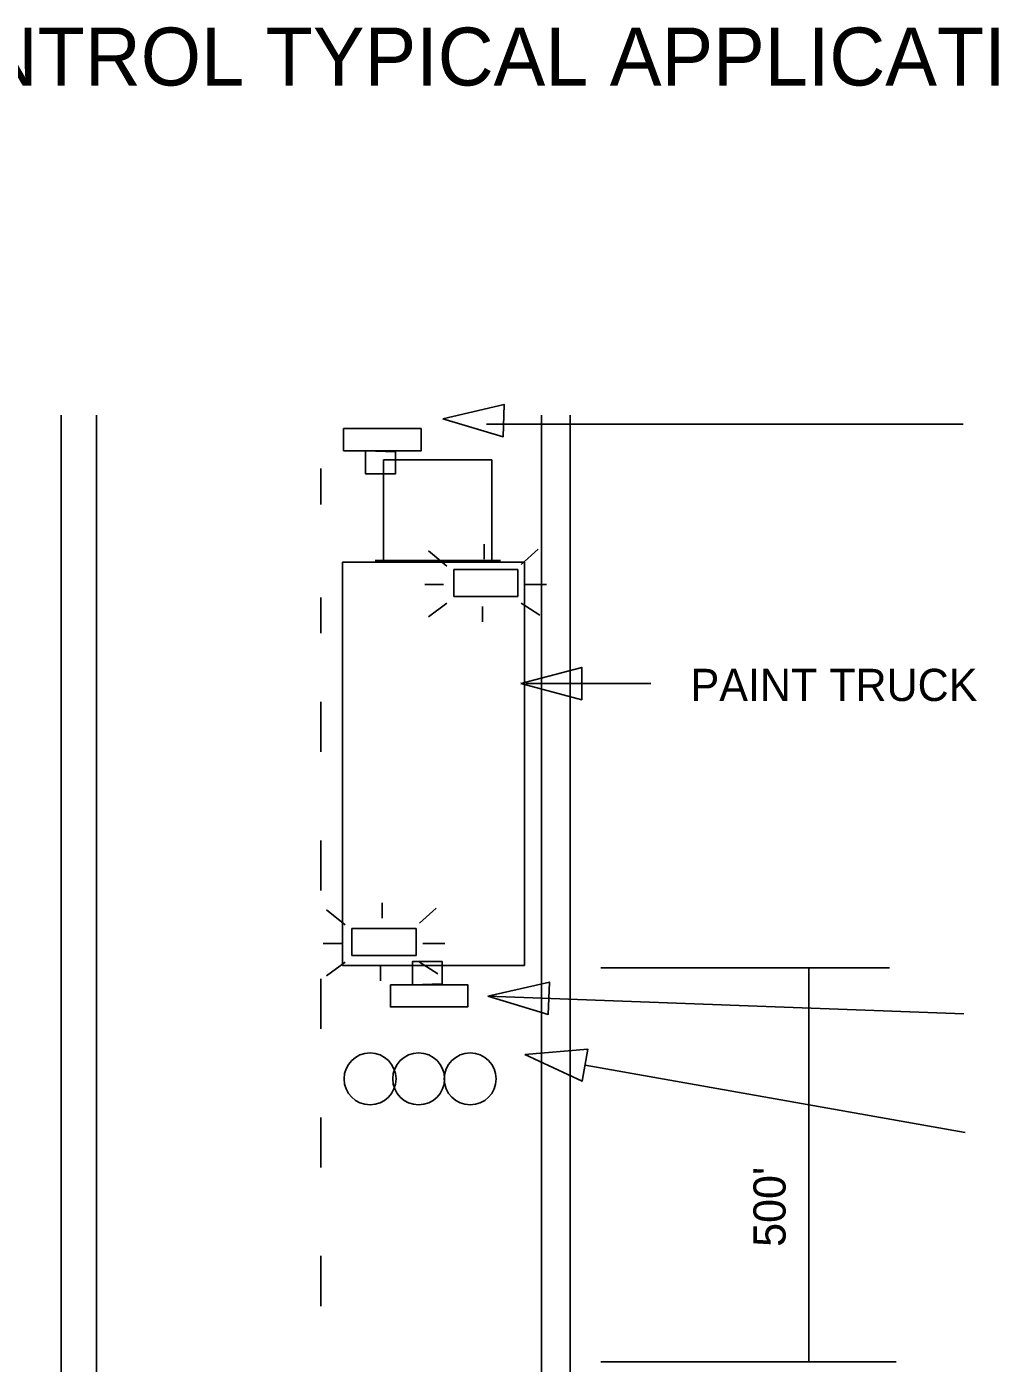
# Model space of a CAD drawing. Extents: x 1531.94 to 1538.58, y 1529.59 to 1539.32.
# Drawn here: x 1534.83 to 1536.631, y 1536.828 to 1539.32 of the extents above; entities that cross this region are included whole.
import ezdxf

# ---------------------------------------------------------------- set-up
doc = ezdxf.new("R2010")
doc.units = 0
for name, color, linetype in [('DETL-DIMS', 7, 'Continuous'), ('DETL-LINE', 7, 'Continuous'), ('DETL-NOTE', 7, 'Continuous'), ('DETL-TITL', 7, 'Continuous'), ('USER-BORD', 7, 'Continuous')]:
    doc.layers.add(name, color=color, linetype=linetype)

# ---------------------------------------------------------------- blocks, each defined once
blk = doc.blocks.new('BAR')
at = {"layer": 'USER-BORD'}
for p, q in [((0.0695, 0.1172), (0.0695, 0.0842)), ((-0.011, 0.0696), (-0.0512, 0.1025)), ((0.15, 0.0732), (0.1866, 0.1062)), ((0.0037, 0.0037), (0.0037, 0.0622)), ((0.0037, 0.0622), (0.1427, 0.0622)), ((0.1427, 0.0622), (0.1427, 0.0037)), ((-0.0183, 0.0293), (-0.0585, 0.0293)), ((0.1573, 0.0293), (0.2049, 0.0293)), ((0.1427, 0.0037), (0.0037, 0.0037)), ((-0.011, -0.011), (-0.0512, -0.0403)), ((0.0658, -0.0183), (0.0658, -0.0513)), ((0.15, -0.011), (0.1902, -0.0366))]:
    blk.add_line(p, q, dxfattribs=at)
blk = doc.blocks.new('SIGN13')
at = {"layer": 'USER-BORD'}
for points in [[(-0.0134, 0.0182), (0.011, 0.0189), (0.011, 0.0371), (-0.0134, 0.0371)], [(-0.0314, 0.0182), (-0.0314, 0), (0.032, 0), (0.032, 0.0182)]]:
    blk.add_lwpolyline(points, close=True, dxfattribs=at)

msp = doc.modelspace()

# ---------------------------------------------------------------- linework, layer by layer
at = {"layer": 'DETL-DIMS'}
for p, q in [((1535.688, 1538.5794), (1536.5772, 1538.5794)), ((1535.7611, 1538.0957), (1535.9943, 1538.0957)), ((1535.9009, 1537.5657), (1536.4396, 1537.5657)), ((1536.2891, 1537.5657), (1536.2891, 1536.831)), ((1535.6904, 1537.5129), (1536.5784, 1537.4797)), ((1535.8717, 1537.3841), (1536.5808, 1537.2583)), ((1536.4521, 1536.831), (1535.9009, 1536.831))]:
    msp.add_line(p, q, dxfattribs=at)
for points in [[(1535.6063, 1538.589), (1535.7208, 1538.6161), (1535.7192, 1538.5558)], [(1535.7518, 1538.0957), (1535.8656, 1538.1258), (1535.8656, 1538.0655)], [(1535.6904, 1537.5129), (1535.8052, 1537.539), (1535.8031, 1537.4788)], [(1535.7597, 1537.404), (1535.877, 1537.4138), (1535.8664, 1537.3545)]]:
    msp.add_lwpolyline(points, close=True, dxfattribs=at)
at = {"layer": 'DETL-LINE'}
for p, q in [((1534.8945, 1538.2527), (1534.8945, 1538.5962)), ((1534.9605, 1538.2527), (1534.9605, 1538.5962)), ((1535.7908, 1538.5962), (1535.7908, 1531.7633)), ((1535.8438, 1538.5962), (1535.8438, 1531.7633)), ((1535.3789, 1538.4298), (1535.3789, 1538.4967)), ((1535.4959, 1538.513), (1535.4959, 1538.3248)), ((1535.6979, 1538.513), (1535.4959, 1538.513)), ((1535.6979, 1538.3248), (1535.6979, 1538.513)), ((1535.4193, 1538.3217), (1535.7588, 1538.3217)), ((1535.4193, 1537.5699), (1535.4193, 1538.3217)), ((1535.4801, 1538.3248), (1535.7138, 1538.3248)), ((1535.521, 1538.3217), (1535.6794, 1538.3217)), ((1535.7588, 1538.3217), (1535.7588, 1537.5699)), ((1534.8945, 1538.2527), (1534.8945, 1531.7633)), ((1534.9605, 1538.2527), (1534.9605, 1531.7633)), ((1535.3789, 1538.1893), (1535.3789, 1538.2562)), ((1535.3789, 1537.9683), (1535.3789, 1538.0617)), ((1535.3789, 1537.71), (1535.3789, 1537.8033)), ((1535.7588, 1537.5699), (1535.4193, 1537.5699)), ((1535.3789, 1537.4516), (1535.3789, 1537.545)), ((1535.7908, 1537.1519), (1535.7908, 1537.4954)), ((1535.8438, 1537.1519), (1535.8438, 1537.4954)), ((1535.3789, 1537.1933), (1535.3789, 1537.2866)), ((1535.3789, 1536.9349), (1535.3789, 1537.0283))]:
    msp.add_line(p, q, dxfattribs=at)
for centre in [(1535.4708, 1537.3585), (1535.5614, 1537.3585), (1535.6575, 1537.3585)]:
    msp.add_circle(centre, 0.0484, dxfattribs=at)

# ---------------------------------------------------------------- block references
for name, p, xscale, yscale in [('SIGN13', (1535.493, 1538.571), 2.2788864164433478, -2.2788864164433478), ('BAR', (1535.6236, 1538.2549), 0.8611764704, 0.8611764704), ('BAR', (1535.4336, 1537.5856), 0.8611764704, 0.8611764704), ('SIGN13', (1535.5802, 1537.4926), 2.2788864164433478, 2.2788864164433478)]:
    msp.add_blockref(name, p, dxfattribs=dict(at, xscale=xscale, yscale=yscale))

# ---------------------------------------------------------------- texts
at = {"layer": 'DETL-NOTE'}
msp.add_text('PAINT TRUCK', height=0.06, dxfattribs=at).set_placement((1536.0686, 1538.0631))
msp.add_text("500'", height=0.06, rotation=90, dxfattribs=at).set_placement((1536.2458, 1537.0453))
at = {"layer": 'DETL-TITL'}
msp.add_text('TEMPORARY TRAFFIC CONTROL TYPICAL APPLICATION', height=0.108, dxfattribs=at).set_placement((1532.925, 1539.2108))

doc.saveas('drawing.dxf')
